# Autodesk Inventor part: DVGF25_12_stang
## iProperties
Created: 2010-04
Part Number: DVGF25_12_stang
Document SubType Name: Modeling
Designer: TB
Mass: 32.1529 g
Surface Area: 95.1363 cm^2
Volume: 32.1529 cm^3
Density: 1 g/cm^3
Author: TB
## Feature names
1. Revolution1
2. Fillet1
3. Revolution2
4. Extrusion1
5. Extrusion2
6. Chamfer1
7. Chamfer2
